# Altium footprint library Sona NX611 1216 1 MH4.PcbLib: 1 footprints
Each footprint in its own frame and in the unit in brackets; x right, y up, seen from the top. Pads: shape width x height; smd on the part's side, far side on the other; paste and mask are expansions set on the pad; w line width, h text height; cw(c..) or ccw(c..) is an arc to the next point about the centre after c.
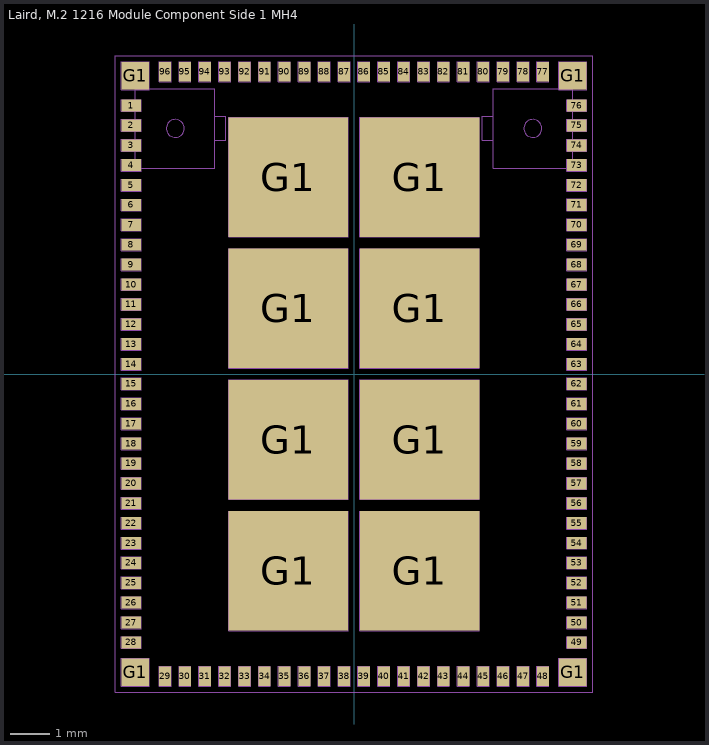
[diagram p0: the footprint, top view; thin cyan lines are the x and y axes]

## Laird, M.2 1216 Module Component Side 1 MH4 [mm] "Laird, M2.1216 Module Component Side 1 MH4"
height 0.4
pads (108):
  rect 0.5x0.3 smd mask+0.051: 1(-5.6,6.75) 2(-5.6,6.25) 3(-5.6,5.75) 4(-5.6,5.25) 5(-5.6,4.75) 6(-5.6,4.25) 7(-5.6,3.75) 8(-5.6,3.25) 9(-5.6,2.75) 10(-5.6,2.25) 11(-5.6,1.75) 12(-5.6,1.25) 13(-5.6,0.75) 14(-5.6,0.25) 15(-5.6,-0.25) 16(-5.6,-0.75) 17(-5.6,-1.25) 18(-5.6,-1.75) 19(-5.6,-2.25) 20(-5.6,-2.75) 21(-5.6,-3.25) 22(-5.6,-3.75) 23(-5.6,-4.25) 24(-5.6,-4.75) 25(-5.6,-5.25) 26(-5.6,-5.75) 27(-5.6,-6.25) 28(-5.6,-6.75) 49(5.6,-6.75) 50(5.6,-6.25) 51(5.6,-5.75) 52(5.6,-5.25) 53(5.6,-4.75) 54(5.6,-4.25) 55(5.6,-3.75) 56(5.6,-3.25) 57(5.6,-2.75) 58(5.6,-2.25) 59(5.6,-1.75) 60(5.6,-1.25) 61(5.6,-0.75) 62(5.6,-0.25) 63(5.6,0.25) 64(5.6,0.75) 65(5.6,1.25) 66(5.6,1.75) 67(5.6,2.25) 68(5.6,2.75) 69(5.6,3.25) 70(5.6,3.75) 71(5.6,4.25) 72(5.6,4.75) 73(5.6,5.25) 74(5.6,5.75) 75(5.6,6.25) 76(5.6,6.75)
  rect 0.3x0.5 smd mask+0.051: 29(-4.749,-7.6) 30(-4.249,-7.6) 31(-3.75,-7.6) 32(-3.249,-7.6) 33(-2.75,-7.6) 34(-2.249,-7.6) 35(-1.749,-7.6) 36(-1.25,-7.6) 37(-0.749,-7.6) 38(-0.25,-7.6) 39(0.251,-7.6) 40(0.751,-7.6) 41(1.25,-7.6) 42(1.751,-7.6) 43(2.25,-7.6) 44(2.751,-7.6) 45(3.251,-7.6) 46(3.75,-7.6) 47(4.251,-7.6) 48(4.75,-7.6) 77(4.75,7.6) 78(4.25,7.6) 79(3.75,7.6) 80(3.25,7.6) 81(2.75,7.6) 82(2.25,7.6) 83(1.75,7.6) 84(1.25,7.6) 85(0.75,7.6) 86(0.25,7.6) 87(-0.25,7.6) 88(-0.75,7.6) 89(-1.25,7.6) 90(-1.75,7.6) 91(-2.25,7.6) 92(-2.75,7.6) 93(-3.25,7.6) 94(-3.75,7.6) 95(-4.25,7.6) 96(-4.75,7.6)
  rect 0.7x0.7 smd mask+0.051: G1(-5.5,-7.5) G1(-5.5,7.5) G1(5.5,-7.5) G1(5.5,7.5)
  rect 3x3 smd mask+0.051: G1(-1.65,4.95) G1(-1.65,-4.95) G1(-1.65,-1.65) G1(-1.65,1.65) G1(1.65,-1.65) G1(1.65,1.65) G1(1.65,4.95) G1(1.65,-4.95)
Top Top Assembly/Bottom Assembly:
  drawing of 452 lines, arcs and shapes, not listed
  text ".Designator" at -0.15,-0.15 h1.27
3D body: height 0.01, standoff 0, extent 4.6,7.35 4.9,7.85
3D body: height 0.01, standoff 0, extent 4.1,7.35 4.4,7.85
3D body: height 0.01, standoff 0, extent 3.6,7.35 3.9,7.85
3D body: height 0.01, standoff 0, extent 3.1,7.35 3.4,7.85
3D body: height 0.01, standoff 0, extent 2.6,7.35 2.9,7.85
3D body: height 0.01, standoff 0, extent 2.1,7.35 2.4,7.85
3D body: height 0.01, standoff 0, extent 1.6,7.35 1.9,7.85
3D body: height 0.01, standoff 0, extent 1.1,7.35 1.4,7.85
3D body: height 0.01, standoff 0, extent 5.15,7.15 5.85,7.85
3D body: height 0.01, standoff 0, extent 5.35,6.6 5.85,6.9
3D body: height 0.01, standoff 0, extent 5.35,6.1 5.85,6.4
3D body: height 0.01, standoff 0, extent 5.35,5.6 5.85,5.9
3D body: height 0.01, standoff 0, extent 5.35,5.1 5.85,5.4
3D body: height 0.01, standoff 0, extent 0.15,3.45 3.15,6.45
3D body: height 0.01, standoff 0, extent 5.35,4.6 5.85,4.9
3D body: height 0.01, standoff 0, extent 5.35,4.1 5.85,4.4
3D body: height 0.01, standoff 0, extent 5.35,3.6 5.85,3.9
3D body: height 0.01, standoff 0, extent 5.35,3.1 5.85,3.4
3D body: height 0.01, standoff 0, extent 5.35,2.6 5.85,2.9
3D body: height 0.01, standoff 0, extent 5.35,2.1 5.85,2.4
3D body: height 0.01, standoff 0, extent 5.35,1.6 5.85,1.9
3D body: height 0.01, standoff 0, extent 0.15,0.15 3.15,3.15
3D body: height 0.01, standoff 0, extent 5.35,1.1 5.85,1.4
3D body: height 0.01, standoff 0, extent 5.35,0.6 5.85,0.9
3D body: height 0.01, standoff 0, extent 5.35,0.1 5.85,0.4
3D body: height 0.01, standoff 0, extent 5.35,-0.4 5.85,-0.1
3D body: height 0.01, standoff 0, extent 5.35,-0.9 5.85,-0.6
3D body: height 0.01, standoff 0, extent 5.35,-1.4 5.85,-1.1
3D body: height 0.01, standoff 0, extent 0.6,7.35 0.9,7.85
3D body: height 0.01, standoff 0, extent 0.1,7.35 0.4,7.85
3D body: height 0.01, standoff 0, extent -0.4,7.35 -0.1,7.85
3D body: height 0.01, standoff 0, extent -0.9,7.35 -0.6,7.85
3D body: height 0.01, standoff 0, extent -1.4,7.35 -1.1,7.85
3D body: height 0.01, standoff 0, extent -1.9,7.35 -1.6,7.85
3D body: height 0.01, standoff 0, extent -2.4,7.35 -2.1,7.85
3D body: height 0.01, standoff 0, extent -2.9,7.35 -2.6,7.85
3D body: height 0.01, standoff 0, extent -4.9,7.35 -4.6,7.85
3D body: height 0.01, standoff 0, extent -4.4,7.35 -4.1,7.85
3D body: height 0.01, standoff 0, extent -3.9,7.35 -3.6,7.85
3D body: height 0.01, standoff 0, extent -3.4,7.35 -3.1,7.85
3D body: height 0.01, standoff 0, extent -5.85,7.15 -5.15,7.85
3D body: height 0.01, standoff 0, extent -5.85,6.6 -5.35,6.9
3D body: height 0.01, standoff 0, extent -5.85,6.1 -5.35,6.4
3D body: height 0.01, standoff 0, extent -5.85,5.6 -5.35,5.9
3D body: height 0.01, standoff 0, extent -5.85,5.1 -5.35,5.4
3D body: height 0.01, standoff 0, extent -3.15,3.45 -0.15,6.45
3D body: height 0.01, standoff 0, extent -5.85,4.6 -5.35,4.9
3D body: height 0.01, standoff 0, extent -5.85,4.1 -5.35,4.4
3D body: height 0.01, standoff 0, extent -5.85,3.6 -5.35,3.9
3D body: height 0.01, standoff 0, extent -5.85,3.1 -5.35,3.4
3D body: height 0.01, standoff 0, extent -5.85,2.6 -5.35,2.9
3D body: height 0.01, standoff 0, extent -5.85,2.1 -5.35,2.4
3D body: height 0.01, standoff 0, extent -5.85,1.6 -5.35,1.9
3D body: height 0.01, standoff 0, extent -3.15,0.15 -0.15,3.15
3D body: height 0.01, standoff 0, extent -5.85,1.1 -5.35,1.4
3D body: height 0.01, standoff 0, extent -5.85,0.6 -5.35,0.9
3D body: height 0.01, standoff 0, extent -5.85,0.1 -5.35,0.4
3D body: height 0.01, standoff 0, extent -5.85,-0.4 -5.35,-0.1
3D body: height 0.01, standoff 0, extent -5.85,-0.9 -5.35,-0.6
3D body: height 0.01, standoff 0, extent -5.85,-1.4 -5.35,-1.1
3D body: height 0.01, standoff 0, extent 0.15,-3.15 3.15,-0.15
3D body: height 0.01, standoff 0, extent -3.15,-3.15 -0.15,-0.15
3D body: height 0.01, standoff 0, extent 5.35,-1.9 5.85,-1.6
3D body: height 0.01, standoff 0, extent 5.35,-2.4 5.85,-2.1
3D body: height 0.01, standoff 0, extent 5.35,-2.9 5.85,-2.6
3D body: height 0.01, standoff 0, extent 5.35,-3.4 5.85,-3.1
3D body: height 0.01, standoff 0, extent 5.35,-3.9 5.85,-3.6
3D body: height 0.01, standoff 0, extent 5.35,-4.4 5.85,-4.1
3D body: height 0.01, standoff 0, extent 5.35,-4.9 5.85,-4.6
3D body: height 0.01, standoff 0, extent 0.15,-6.45 3.15,-3.45
3D body: height 0.01, standoff 0, extent -3.15,-6.45 -0.15,-3.45
3D body: height 0.01, standoff 0, extent 5.35,-5.4 5.85,-5.1
3D body: height 0.01, standoff 0, extent 5.35,-5.9 5.85,-5.6
3D body: height 0.01, standoff 0, extent 5.35,-6.4 5.85,-6.1
3D body: height 0.01, standoff 0, extent 5.35,-6.9 5.85,-6.6
3D body: height 0.01, standoff 0, extent 5.15,-7.85 5.85,-7.15
3D body: height 0.01, standoff 0, extent 4.6,-7.85 4.9,-7.35
3D body: height 0.01, standoff 0, extent 2.6,-7.85 2.9,-7.35
3D body: height 0.01, standoff 0, extent 3.1,-7.85 3.4,-7.35
3D body: height 0.01, standoff 0, extent 3.6,-7.85 3.9,-7.35
3D body: height 0.01, standoff 0, extent 4.1,-7.85 4.4,-7.35
3D body: height 0.01, standoff 0, extent 2.1,-7.85 2.4,-7.35
3D body: height 0.01, standoff 0, extent 1.6,-7.85 1.9,-7.35
3D body: height 0.01, standoff 0, extent 1.1,-7.85 1.4,-7.35
3D body: height 0.01, standoff 0, extent 0.6,-7.85 0.9,-7.35
3D body: height 0.01, standoff 0, extent 0.1,-7.85 0.4,-7.35
3D body: height 0.01, standoff 0, extent -0.4,-7.85 -0.1,-7.35
3D body: height 0.01, standoff 0, extent -0.9,-7.85 -0.6,-7.35
3D body: height 0.01, standoff 0, extent -1.4,-7.85 -1.1,-7.35
3D body: height 0.01, standoff 0, extent -1.9,-7.85 -1.6,-7.35
3D body: height 0.01, standoff 0, extent -2.4,-7.85 -2.1,-7.35
3D body: height 0.01, standoff 0, extent -2.9,-7.85 -2.6,-7.35
3D body: height 0.01, standoff 0, extent -3.4,-7.85 -3.1,-7.35
3D body: height 0.01, standoff 0, extent -3.9,-7.85 -3.6,-7.35
3D body: height 0.01, standoff 0, extent -4.4,-7.85 -4.1,-7.35
3D body: height 0.01, standoff 0, extent -4.9,-7.85 -4.6,-7.35
3D body: height 0.01, standoff 0, extent -5.85,-7.85 -5.15,-7.15
3D body: height 0.01, standoff 0, extent -5.85,-6.9 -5.35,-6.6
3D body: height 0.01, standoff 0, extent -5.85,-6.4 -5.35,-6.1
3D body: height 0.01, standoff 0, extent -5.85,-5.4 -5.35,-5.1
3D body: height 0.01, standoff 0, extent -5.85,-5.9 -5.35,-5.6
3D body: height 0.01, standoff 0, extent -5.85,-1.9 -5.35,-1.6
3D body: height 0.01, standoff 0, extent -5.85,-2.4 -5.35,-2.1
3D body: height 0.01, standoff 0, extent -5.85,-2.9 -5.35,-2.6
3D body: height 0.01, standoff 0, extent -5.85,-4.9 -5.35,-4.6
3D body: height 0.01, standoff 0, extent -5.85,-4.4 -5.35,-4.1
3D body: height 0.01, standoff 0, extent -5.85,-3.9 -5.35,-3.6
3D body: height 0.01, standoff 0, extent -5.85,-3.4 -5.35,-3.1
3D body "941-03396__PRJ,_Sona_NX611_and_NX612,_M_2_1216_Module__940-00275_PCBA,_Module,_Sona_NX611_M_2_1216,_1_MHF4_.SLDPRT": height 1.73, standoff 0, extent -6,-8 6,8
